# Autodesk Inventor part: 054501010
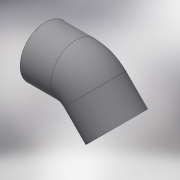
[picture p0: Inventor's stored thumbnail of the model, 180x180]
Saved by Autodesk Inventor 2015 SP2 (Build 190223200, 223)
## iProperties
Created: 2017-10
Part Number: 054501010
Material: Generic
Description: PLASSON THREADED 45° ELBOW HF 1"
Document SubType Name: Modeling
Designer: KIM
Mass: 28.222 g
Surface Area: 130.708 cm^2
Volume: 28.222 cm^3
Density: 1 g/cm^3
Appearance: Default
Author: KIM
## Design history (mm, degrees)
derived "054501.ipt"
feature "Solid1::054501.ipt"
tag "TaggingFeature1"
body "Solid1"
other parameters: "d7" = 0.30291, "d9" = 39, "d13" = 135 deg, "d18" = 8, "d19" = 45 deg, "d20" = 30.291, "d22" = 0, "d28" = 28, "d29" = 30.291, "d31" = 0, "d32" = 27.2619, "d33" = 45 deg, "E_" = 39, "Z_" = 8, "G_" = 30.291
